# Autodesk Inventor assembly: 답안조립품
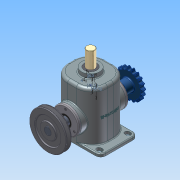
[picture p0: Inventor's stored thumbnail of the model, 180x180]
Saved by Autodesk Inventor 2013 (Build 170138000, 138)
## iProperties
Created: 2014-12
Part Number: 답안조립품
Document SubType Name: Assembly
Designer: Administrator
Author: Administrator
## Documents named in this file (15)
- C:\Users\Administrator\Desktop\341209V1009\341209V1009\답안조립품.iam
- C:\Users\Administrator\Desktop\341209V1009\341209V1009\본체.ipt
- C:\Users\Administrator\Desktop\341209V1009\341209V1009\M4x0.5.ipt
- C:\Users\Administrator\Desktop\341209V1009\341209V1009\커버.ipt
- C:\Users\Administrator\Desktop\341209V1009\341209V1009\오일실.ipt
- C:\Users\Administrator\Desktop\341209V1009\341209V1009\편심축.ipt
- C:\Users\Administrator\Desktop\341209V1009\341209V1009\키 8x8.ipt
- C:\Users\Administrator\Desktop\341209V1009\341209V1009\멈춤링.ipt
- C:\Users\Administrator\Desktop\341209V1009\341209V1009\베어링 6205.ipt
- C:\Users\Administrator\Desktop\341209V1009\341209V1009\V-벨트풀리.ipt
- C:\Users\Administrator\Desktop\341209V1009\341209V1009\멈춤나사 M5x0.5.ipt
- C:\Users\Administrator\Desktop\341209V1009\341209V1009\체인 스프로킷.ipt
- C:\Users\Administrator\Desktop\341209V1009\341209V1009\부시.ipt
- C:\Users\Administrator\Desktop\341209V1009\341209V1009\스프링-[가변].ipt
- C:\Users\Administrator\Desktop\341209V1009\341209V1009\슬라이드.ipt
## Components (8 placed, 3 different names)
1. V-벨트풀리:1 — 플러쉬:1, 각도:1
2. 5-체인 스프로킷:1 — 플러쉬:2
3. M4x0.5:1
4. M4x0.5:2
5. M4x0.5:3
6. M4x0.5:4
7. M4x0.5:5
8. M4x0.5:6
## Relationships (3: Flush 2, Angle 1)
- 플러쉬:1 [Flush]: V-벨트풀리:1
- 플러쉬:2 [Flush]: 5-체인 스프로킷:1
- 각도:1 [Angle]: V-벨트풀리:1
